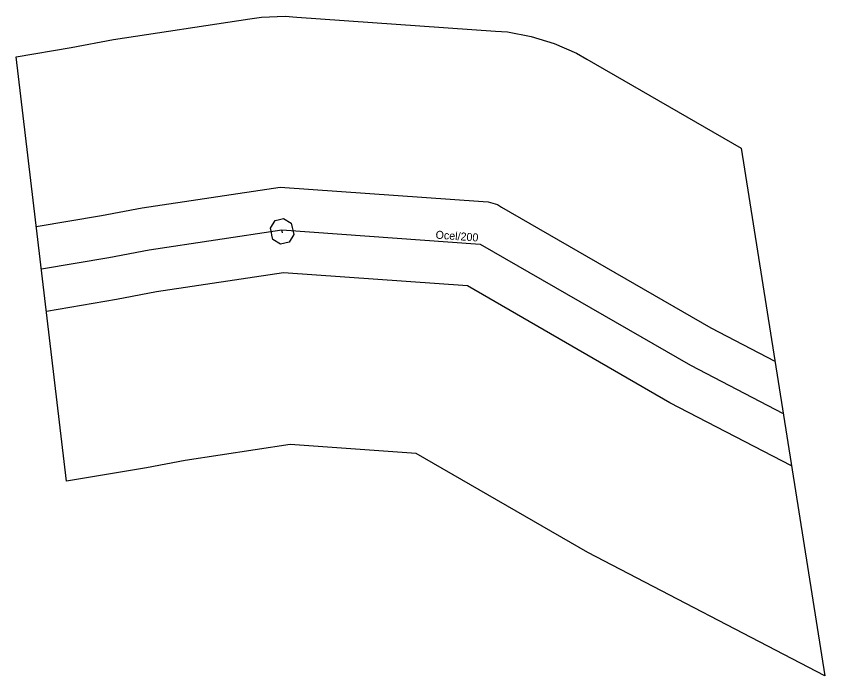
# Model space of a CAD drawing. Extents: x -866668 to -866425, y -1041329 to -1040263.
# Drawn here: x -866561.8 to -866486.1, y -1041329.5 to -1041267.7 of the extents above; entities that cross this region are included whole.
import ezdxf

# ---------------------------------------------------------------- set-up
doc = ezdxf.new("R2010")
doc.units = 0
for name, color, linetype in [('1', 7, 'Continuous'), ('34', 7, 'Continuous'), ('40', 7, 'Continuous'), ('56', 7, 'Continuous'), ('8', 7, 'Continuous')]:
    doc.layers.add(name, color=color, linetype=linetype)

msp = doc.modelspace()

# ---------------------------------------------------------------- linework, layer by layer
at = {"layer": '1'}
for p, q in [((-866550.042, -1041285.626), (-866537.118, -1041283.679)), ((-866537.118, -1041283.679), (-866518.077, -1041285.03)), ((-866518.077, -1041285.03), (-866517.624, -1041285.062)), ((-866517.624, -1041285.062), (-866516.755, -1041285.328)), ((-866553.857, -1041286.353), (-866550.042, -1041285.626)), ((-866516.755, -1041285.328), (-866516.361, -1041285.555)), ((-866516.361, -1041285.555), (-866496.747, -1041296.872)), ((-866559.953, -1041287.38), (-866553.857, -1041286.353)), ((-866536.802, -1041291.721), (-866548.698, -1041293.514)), ((-866519.561, -1041292.945), (-866536.802, -1041291.721)), ((-866500.593, -1041303.888), (-866519.561, -1041292.945)), ((-866552.443, -1041294.227), (-866559.01, -1041295.334)), ((-866548.698, -1041293.514), (-866552.443, -1041294.227)), ((-866496.747, -1041296.872), (-866490.759, -1041299.987)), ((-866489.199, -1041309.815), (-866500.593, -1041303.888))]:
    msp.add_line(p, q, dxfattribs=at)
msp.add_lwpolyline([(-866557.122, -1041311.241), (-866561.841, -1041271.472), (-866556.683, -1041270.603), (-866552.732, -1041269.851), (-866539.94, -1041267.923), (-866538.849, -1041267.759), (-866536.645, -1041267.672), (-866535.544, -1041267.75), (-866516.944, -1041269.07), (-866515.815, -1041269.15), (-866513.588, -1041269.564), (-866511.423, -1041270.227), (-866509.346, -1041271.13), (-866508.365, -1041271.696), (-866493.927, -1041280.026), (-866486.078, -1041329.475), (-866508.287, -1041317.922), (-866524.367, -1041308.644), (-866536.168, -1041307.806), (-866546.008, -1041309.289), (-866549.617, -1041309.977)], close=True, dxfattribs=at)
at = {"layer": '34'}
msp.add_lwpolyline([(-866559.482, -1041291.357), (-866553.15, -1041290.29), (-866549.37, -1041289.57), (-866536.96, -1041287.7), (-866518.36, -1041289.02), (-866498.67, -1041300.38), (-866489.979, -1041304.901)], dxfattribs=at)
at = {"layer": '56'}
msp.add_lwpolyline([(-866536.9, -1041287.96), (-866536.96, -1041287.7)], dxfattribs=at)
at = {"layer": '8'}
msp.add_lwpolyline([(-866537.781, -1041288.588), (-866537.874, -1041288.185), (-866537.934, -1041287.925), (-866538.027, -1041287.521), (-866537.588, -1041286.819), (-866537.185, -1041286.726), (-866536.781, -1041286.633), (-866536.079, -1041287.072), (-866535.986, -1041287.475), (-866535.926, -1041287.735), (-866535.833, -1041288.139), (-866536.272, -1041288.841), (-866536.675, -1041288.934), (-866537.079, -1041289.027)], close=True, dxfattribs=at)

# ---------------------------------------------------------------- texts
at = {"layer": '40'}
msp.add_text('Ocel/200', height=0.75, rotation=355.94065, dxfattribs=at).set_placement((-866522.567, -1041288.507))

doc.saveas('drawing.dxf')
